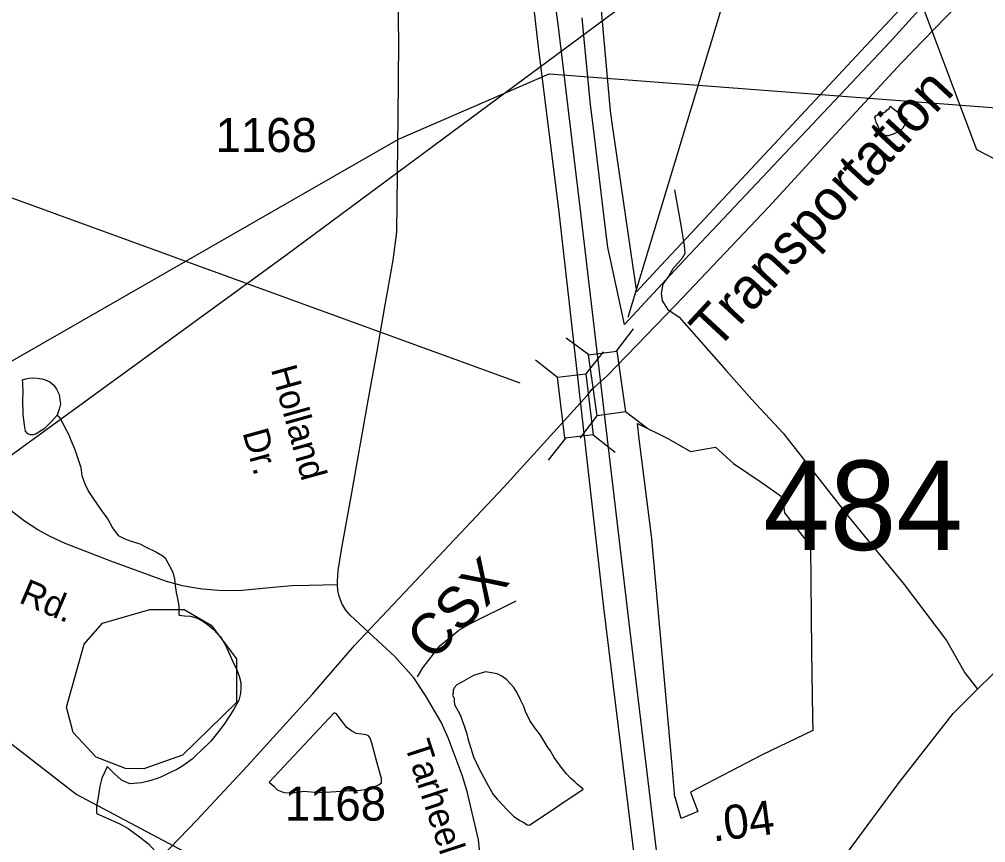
# Model space of a CAD drawing. Extents: x 2082433 to 2279600, y 546599 to 755198.
# Drawn here: x 2139852 to 2143397, y 601095 to 604115 of the extents above; entities that cross this region are included whole.
import ezdxf

# ---------------------------------------------------------------- set-up
doc = ezdxf.new("R2010")
doc.units = 0
for name, color, linetype in [('Exist Boundary Political City Limit New', 7, 'Continuous'), ('Exist Boundary Political Fire Districts', 7, 'Continuous'), ('Exist Hydrographic Creek Single Shore', 7, 'Continuous'), ('Exist Hydrographic Misc Water Feature', 7, 'Continuous'), ('Exist Hydrographic Pond Under 1500 Sq Ft', 7, 'Continuous'), ('Exist Railroad Mainline', 7, 'Continuous'), ('Exist Railroad Mainline Label', 7, 'Continuous'), ('Exist Road Non-System Type 51', 7, 'Continuous'), ('Exist Road Non-System Type 51 Label', 7, 'Continuous'), ('Exist Road Primary Interstate Divided Center Attributed', 7, 'Continuous'), ('Exist Road Primary Interstate Structure Standard Bridge CELL', 7, 'Continuous'), ('Exist Road Primary Interstate Structure Standard Bridge Number Label', 7, 'Continuous'), ('Exist Road Primary US Attributed', 7, 'Continuous'), ('Exist Road Primary US Mileage Hundredths English Label', 7, 'Continuous'), ('Exist Road Secondary Structure Standard Bridge Number Label', 7, 'Continuous'), ('Exist Road Secondary Type 51 Attributed', 7, 'Continuous'), ('Exist Road Secondary Type 51 Label', 7, 'Continuous'), ('Exist Road Secondary Type 51 Number Label', 7, 'Continuous'), ('Exist Utilities Electrical Transmission Line', 7, 'Continuous'), ('Map Preparation Boundary City Limit Buffer Line', 7, 'Continuous')]:
    doc.layers.add(name, color=color, linetype=linetype)

msp = doc.modelspace()

# ---------------------------------------------------------------- linework, layer by layer
at = {"layer": 'Exist Boundary Political City Limit New'}
for points in [[(2141956.2, 604475.9), (2142018.8, 603779.5), (2142025.5, 603733.8), (2142101.2, 603214.7), (2142115.8, 603115.7), (2142205.5, 603212.1), (2142282.5, 603294.6), (2143007, 604072.2), (2143139, 604213.8)], [(2143198, 604200.7), (2143043.2, 604030.7), (2143026.2, 604011.9), (2142271, 603210.5)], [(2142271, 603210.5), (2142072, 602996.3), (2142023.8, 603216.6), (2142022.5, 603222.9), (2142010.5, 603278.3), (2141996, 603397.6), (2141958.8, 603705.6), (2141947, 603802.1), (2141923.8, 604041.9), (2141920, 604080.1), (2141916, 604120.9)], [(2142233, 602576.2), (2142314.2, 602530.2), (2142405.5, 602546.1), (2142472, 602486.4), (2142576.8, 602414.9), (2142651.5, 602362.6), (2142658, 602305.4), (2142753.8, 602183.1), (2142756.5, 601929), (2142758, 601797.4), (2142761.5, 601554.9), (2142762.2, 601507.3), (2142576.8, 601417.4), (2142313.8, 601280.9), (2142340.2, 601209.5), (2142279.2, 601183.9), (2142258, 601261.8), (2142256.5, 601261), (2142247, 601378.5), (2142172, 602210.6), (2142126, 602576.2), (2142119.2, 602632.8), (2142233, 602576.2)]]:
    msp.add_lwpolyline(points, dxfattribs=at)
at = {"layer": 'Exist Boundary Political Fire Districts'}
msp.add_lwpolyline([(2125185.8, 609236.3), (2127409.2, 608956.3), (2130289.8, 608255.9), (2136376.8, 600637.7), (2139465.5, 602656.7), (2141242.8, 603675.4), (2141795.1, 603915), (2144979.3, 603672.9), (2148226.1, 607636.4), (2150227.4, 608573.5)], dxfattribs=at)
at = {"layer": 'Exist Hydrographic Creek Single Shore'}
msp.add_lwpolyline([(2143929.9, 600141.8), (2143945.9, 600200.5), (2144129, 600324.8), (2144261.1, 600551.7), (2144234, 600985.3), (2144012.4, 602131.7), (2143753, 602490.9), (2143635.1, 602722.9), (2143643.1, 602847.4), (2143774.9, 602998.9), (2143782.9, 603182.5), (2143682, 603424), (2143615, 603507.3), (2143364, 603637), (2143154, 604195.8), (2142718.9, 604526), (2142516.9, 604966.3), (2142400, 605050.7)], dxfattribs=at)
at = {"layer": 'Exist Hydrographic Misc Water Feature'}
for points in [[(2143046.7, 603796.2), (2143106.8, 603748.6), (2143102.7, 603734.6), (2143092.8, 603716.2), (2143086.7, 603710.2), (2143076.8, 603702.4), (2143056.7, 603694.1), (2143038.9, 603688.3), (2143033, 603688.4), (2143025.2, 603689.9), (2143017.2, 603696), (2143010.6, 603700.2), (2143002.8, 603720.1), (2142994.8, 603737.9), (2142992.6, 603748), (2142990.5, 603756), (2142994.6, 603761.9), (2143028.9, 603776.2), (2143034.4, 603782.2), (2143042.8, 603788.3), (2143046.7, 603796.2)], [(2140618.9, 600976.4), (2140058.9, 601273.1), (2139824.9, 601455.1), (2139165.9, 601661.9), (2138548.8, 601808.9), (2138273.9, 601926), (2138039.7, 602098.1), (2137888.8, 602288.1), (2137686.8, 602781), (2137484.8, 603162.3), (2137342.7, 603362), (2137175.8, 603486.7), (2137066.7, 603518.5), (2136775.7, 603508)], [(2139990.4, 602663), (2139970.5, 602640.8), (2139942.4, 602613.1), (2139913.1, 602594.8), (2139902.6, 602590.7), (2139892.8, 602590.6), (2139882.9, 602594.5), (2139874.7, 602604.7), (2139870.8, 602626.7), (2139866.3, 602666.7), (2139864.1, 602716.6), (2139866.1, 602746.7), (2139864.1, 602780.6), (2139863.9, 602792.4), (2139875.8, 602796.7), (2139887.9, 602798.5), (2139899.8, 602800.8), (2139917.8, 602798.9), (2139934, 602796.8), (2139946.1, 602793), (2139963.9, 602785), (2139978.1, 602773.1), (2139988.1, 602759.1), (2139998.4, 602739.2), (2140000, 602719.1), (2140002.5, 602705), (2139998.4, 602685.3), (2139990.4, 602663)], [(2139990.4, 602663), (2139998.4, 602657.4), (2140010.7, 602635.2), (2140024.8, 602607.1), (2140032.8, 602591.3), (2140041, 602571.4), (2140052.9, 602543.7), (2140061.1, 602519.2), (2140068.9, 602497.4), (2140077.3, 602471.4), (2140081.4, 602441.6), (2140091.7, 602411.6), (2140105.6, 602383.6), (2140125.7, 602353.8), (2140136, 602338), (2140155.9, 602309.8), (2140176.4, 602282.1), (2140194, 602250.2), (2140214.5, 602222.3), (2140238.3, 602210.2), (2140258.2, 602202.3), (2140294.3, 602190.8), (2140314.2, 602180.9), (2140354.8, 602161), (2140378.8, 602147.2), (2140388.4, 602139.2), (2140390.9, 602133.2), (2140403, 602111.1), (2140414.6, 602087.4), (2140421, 602061.3), (2140423.3, 602039.1), (2140426.9, 602013.4), (2140431.5, 601991.2), (2140437.4, 601963.6), (2140437.4, 601951.4), (2140437.4, 601933.5), (2140437.6, 601929.4)], [(2140437.6, 601929.4), (2140457.3, 601927.3), (2140479.4, 601925.5), (2140501.6, 601919.8), (2140525.4, 601907.6), (2140541.8, 601895.8), (2140561.7, 601879.8), (2140579.9, 601860.1), (2140589.8, 601850.1), (2140607.8, 601820.2), (2140634.3, 601762.2), (2140642.2, 601744.4), (2140648.4, 601732.5), (2140658.4, 601706.2), (2140664.8, 601682.6), (2140664.6, 601664.3), (2140662.8, 601642.3), (2140656.6, 601618.5), (2140637.1, 601582.6), (2140603.3, 601530.1), (2140579.1, 601498), (2140553.7, 601467.8), (2140517.6, 601431.9), (2140501.6, 601417.7), (2140485.8, 601401.8), (2140451.6, 601377.4), (2140430, 601363.6), (2140402.1, 601351.2), (2140373.8, 601337.2), (2140354.2, 601329.3), (2140326.1, 601321), (2140300.4, 601315.1), (2140258.6, 601310.9), (2140248.5, 601314.8), (2140226.4, 601324.7), (2140197.9, 601350.5), (2140174.3, 601374.3)], [(2140174.3, 601374.3), (2140170, 601366.4), (2140164.3, 601352.3), (2140154.6, 601332.3), (2140146.6, 601302.3), (2140142.5, 601270.1), (2140138.8, 601248.3), (2140134.5, 601230.3), (2140134.5, 601220.1), (2140134.7, 601206.3), (2140134.5, 601202.3)], [(2140134.5, 601202.3), (2140220.9, 601164.5), (2140251.2, 601146.9), (2140287.3, 601120.8), (2140325.2, 601091.2), (2140351.1, 601063.3), (2140379.6, 601027.3), (2140411.8, 600985.6), (2140465.9, 600925.9), (2140513.9, 600882.1), (2140523.9, 600876.2)]]:
    msp.add_lwpolyline(points, dxfattribs=at)
at = {"layer": 'Exist Hydrographic Pond Under 1500 Sq Ft'}
for points in [[(2140241.8, 601367.9), (2140133.9, 601409.5), (2140049.9, 601499.7), (2140024.8, 601592.1), (2140089.8, 601823.7), (2140156.9, 601901), (2140330.8, 601950), (2140455.9, 601950.7), (2140555.9, 601893), (2140648.8, 601769.7), (2140648.8, 601609), (2140449.9, 601416.1), (2140308.8, 601366.5), (2140241.8, 601367.9)], [(2141919.9, 601292), (2141909.7, 601300), (2141897.8, 601310), (2141889.8, 601318.1), (2141873.4, 601331.9), (2141859.4, 601347.8), (2141839.8, 601371.9), (2141823.3, 601393.8), (2141813.3, 601407.5), (2141799.4, 601433.5), (2141788.9, 601447.3), (2141763.3, 601489.3), (2141742.8, 601517.1), (2141724.9, 601542.9), (2141708.5, 601577), (2141702.6, 601595), (2141690.5, 601618.7), (2141678.2, 601644.9), (2141666.3, 601665), (2141639.8, 601692.8), (2141622.2, 601706.5), (2141604.4, 601714.5), (2141584.3, 601718.3), (2141562.3, 601722.4), (2141537.9, 601714.4), (2141517.8, 601708.1), (2141474.4, 601683.8), (2141456.5, 601674), (2141446.3, 601663.7), (2141442.6, 601653.8), (2141442.6, 601643.6), (2141440.3, 601635.8), (2141446.9, 601625.9), (2141446.5, 601613.8), (2141448.7, 601601.7), (2141468.8, 601563.8), (2141484.8, 601520), (2141492.8, 601494.1), (2141496.9, 601478), (2141517.6, 601410.4), (2141537.7, 601368.4), (2141565.6, 601316.4), (2141590.2, 601272.5), (2141604.1, 601254.6), (2141642.3, 601214.8), (2141664.6, 601193.1), (2141688.2, 601177), (2141702.2, 601169.2), (2141714.5, 601161.2), (2141722.7, 601159.2), (2141919.9, 601292)], [(2141006.8, 601572.1), (2140768.4, 601316.9), (2140786.2, 601301.2), (2140798.1, 601288.9), (2140816.3, 601281.3), (2140824.5, 601279.2), (2140854.5, 601277.6), (2140894.1, 601283.7), (2140952.1, 601279.8), (2140994.1, 601282), (2141032.1, 601284.4), (2141062, 601286.3), (2141082.1, 601286.5), (2141102.4, 601288.3), (2141118, 601290.4), (2141138.3, 601294.6), (2141156.3, 601300.8), (2141172.1, 601308.6), (2141179.9, 601314.7), (2141179.9, 601330.9), (2141163.9, 601386.9), (2141153.2, 601428.6), (2141145.4, 601460.6), (2141139.1, 601478.6), (2141131.5, 601488.7), (2141117.1, 601492.5), (2141086.8, 601496.3), (2141071.2, 601504.3), (2141053, 601518), (2141025.1, 601553.9), (2141015, 601568), (2141006.8, 601572.1)]]:
    msp.add_lwpolyline(points, dxfattribs=at)
at = {"layer": 'Exist Railroad Mainline'}
for points in [[(2142008.3, 602807.8), (2142260.1, 603068.4), (2142600.3, 603425.8), (2142847.2, 603694.8), (2143087.8, 603955.7), (2143290.8, 604164.6), (2143495.9, 604377.4), (2143705, 604580.3), (2144004.8, 604884), (2144236.9, 605087.5)], [(2141935, 602736), (2141952.8, 602758.6), (2142008.3, 602807.8)], [(2141139.2, 601879.4), (2141368.4, 602122.7), (2141629.2, 602399.8), (2141935, 602736)], [(2139743.5, 600355.6), (2140058, 600703.5), (2140306.3, 600973.6), (2140502.7, 601177.8), (2140687.7, 601376.4), (2140927.3, 601639.9), (2141081.3, 601818.2), (2141139.2, 601879.4)]]:
    msp.add_lwpolyline(points, dxfattribs=at)
at = {"layer": 'Exist Road Non-System Type 51'}
for points in [[(2142254.6, 603489.5), (2142278.6, 603359.7), (2142291, 603285), (2142293, 603256.9), (2142285.4, 603241.8), (2142249.4, 603200.4), (2142233.7, 603174.3), (2142211.7, 603144.1), (2142205.8, 603110.3), (2142210.2, 603082.9), (2142230.7, 603050.4), (2142272.6, 603023.1), (2142444.3, 602826.6), (2142538.3, 602720.7), (2142653.6, 602597.6), (2142895.4, 602288.4), (2143097.8, 602042.3), (2143252.5, 601837.3), (2143319.8, 601718.3), (2143366, 601658.2)], [(2141312.7, 601704), (2141331.4, 601736.5), (2141394.5, 601817.3), (2141463.5, 601874.5), (2141504.9, 601898.2), (2141674.4, 601982.9)]]:
    msp.add_lwpolyline(points, dxfattribs=at)
at = {"layer": 'Exist Road Primary Interstate Divided Center Attributed'}
for points in [[(2142289.3, 600244.4), (2142193.2, 601036.8), (2142088.2, 601902), (2141909.3, 603424.4), (2141828.1, 604097.7), (2141783.1, 604420.9), (2141758.2, 604671.4), (2141713.3, 604944.9), (2141667.4, 605151.5), (2141604.3, 605340.8), (2141289.8, 606102.6), (2140968.9, 606854.4), (2140672.2, 607566.5), (2140580.2, 607781.9), (2140439.4, 608117.8)], [(2140405.1, 608012.7), (2140582, 607576.6), (2140889.2, 606863.6), (2141159.6, 606209.1), (2141502.9, 605392.5), (2141566, 605203.1), (2141615.8, 605031), (2141646.4, 604902.9), (2141677, 604700.1), (2141755.4, 604013.5), (2141829, 603418.7), (2141994.4, 601957.5), (2142217.1, 600147.6)]]:
    msp.add_lwpolyline(points, dxfattribs=at)
at = {"layer": 'Exist Road Primary Interstate Structure Standard Bridge CELL'}
for p, q in [((2142042.2, 602898.4), (2142104.2, 602980.5)), ((2141940.3, 602884.1), (2141858.2, 602946.1)), ((2141993.9, 602895.9), (2141930.4, 602815)), ((2141745, 602865.9), (2141825.9, 602802.4)), ((2142157.4, 602613.5), (2142075.3, 602675.5)), ((2141909.1, 602578.8), (2141971, 602660.9)), ((2141854.7, 602578.9), (2141791.2, 602497.9)), ((2141956.9, 602591.2), (2142037.8, 602527.6))]:
    msp.add_line(p, q, dxfattribs=at)
for points in [[(2141971, 602660.9), (2141939.9, 602884.1), (2142044.1, 602898.6), (2142075.3, 602675.5)], [(2141930.4, 602815), (2141957.3, 602591.2), (2141852.8, 602578.6), (2141825.9, 602802.4)]]:
    msp.add_lwpolyline(points, close=True, dxfattribs=at)
at = {"layer": 'Exist Road Primary Interstate Structure Standard Bridge Number Label'}
for p, q in [((2142085.5, 603023), (2142801, 605389.9)), ((2141689.2, 602780.9), (2139421.4, 603606.5))]:
    msp.add_line(p, q, dxfattribs=at)
at = {"layer": 'Exist Road Primary US Attributed'}
msp.add_lwpolyline([(2142431, 600436.1), (2142771.9, 600899.9), (2142962.4, 601157.6), (2143079.5, 601316.3), (2143276.8, 601569.3), (2143366, 601658.2), (2143471.9, 601760.5), (2143832.3, 602076.7), (2144263.2, 602457.9), (2144581.2, 602737.3), (2144811, 602936.1), (2144937.1, 603035.2), (2145061.1, 603119.9), (2145064.1, 603117.9), (2145164.1, 603180.5)], dxfattribs=at)
at = {"layer": 'Exist Road Secondary Type 51 Attributed'}
for points in [[(2141018.4, 602054.7), (2141021.9, 602094.1), (2141035.1, 602176.9), (2141071.2, 602378.3), (2141129, 602703.4), (2141163.9, 602898.5), (2141192.6, 603061.1), (2141222.7, 603231.3), (2141237.1, 603334.6), (2141241.6, 603757.2), (2141244.4, 604030.7), (2141241.8, 604189.5)], [(2141019, 602041), (2140913.4, 602038.4), (2140851.1, 602036.9), (2140810.2, 602033.5), (2140667.8, 602020.8), (2140628.5, 602019.4), (2140582.5, 602020.6), (2140523.8, 602025.4), (2140484, 602031.2), (2140449.9, 602037.5), (2140391.1, 602052.8), (2140187.5, 602127.3), (2140020.2, 602192.2), (2139963, 602218.9), (2139920.2, 602242.7), (2139871, 602274.6), (2139822.4, 602312.3)], [(2141548.4, 600984.3), (2141535.7, 601105.9), (2141494, 601282.7), (2141476.8, 601343.5), (2141425.1, 601480.4), (2141398.8, 601537.6), (2141341.7, 601635.5), (2141299, 601699.9), (2141229.2, 601777.9), (2141134.9, 601865), (2141065.1, 601929.3), (2141049.8, 601947.9), (2141035.1, 601972), (2141025.2, 601999.2), (2141020.7, 602020.4), (2141019, 602041), (2141018.4, 602054.7)]]:
    msp.add_lwpolyline(points, dxfattribs=at)
at = {"layer": 'Exist Utilities Electrical Transmission Line'}
msp.add_lwpolyline([(2135510.3, 599346), (2136050.3, 599742.2), (2136793.7, 600289.3), (2137523.2, 600836.5), (2138250.6, 601365.5), (2138619.3, 601637), (2138990, 601910.6), (2139364.7, 602184), (2139739.4, 602457.6), (2140486.9, 603000.7), (2140829.8, 603250.2), (2141575.1, 603803.2), (2141969.6, 604095), (2142338.3, 604368.5), (2142712.9, 604640), (2143476.4, 605209.1), (2143859, 605478.7), (2144235.8, 605746.2), (2144606.6, 606003.9), (2144985.1, 606269.4), (2145363.9, 606534.9), (2145742.6, 606790.6), (2146119.5, 607050.1), (2146496.2, 607313.6)], dxfattribs=at)
at = {"layer": 'Map Preparation Boundary City Limit Buffer Line'}
for points in [[(2141956.2, 604475.9), (2142018.8, 603779.5), (2142025.5, 603733.8), (2142101.2, 603214.7), (2142115.8, 603115.7), (2142205.5, 603212.1), (2142282.5, 603294.6), (2143007, 604072.2), (2143139, 604213.8)], [(2143198, 604200.7), (2143043.2, 604030.7), (2143026.2, 604011.9), (2142271, 603210.5)], [(2142271, 603210.5), (2142072, 602996.3), (2142023.8, 603216.6), (2142022.5, 603222.9), (2142010.5, 603278.3), (2141996, 603397.6), (2141958.8, 603705.6), (2141947, 603802.1), (2141923.8, 604041.9), (2141920, 604080.1), (2141916, 604120.9)], [(2142233, 602576.2), (2142314.2, 602530.2), (2142405.5, 602546.1), (2142472, 602486.4), (2142576.8, 602414.9), (2142651.5, 602362.6), (2142658, 602305.4), (2142753.8, 602183.1), (2142756.5, 601929), (2142758, 601797.4), (2142761.5, 601554.9), (2142762.2, 601507.3), (2142576.8, 601417.4), (2142313.8, 601280.9), (2142340.2, 601209.5), (2142279.2, 601183.9), (2142258, 601261.8), (2142256.5, 601261), (2142247, 601378.5), (2142172, 602210.6), (2142126, 602576.2), (2142119.2, 602632.8), (2142233, 602576.2)]]:
    msp.add_lwpolyline(points, dxfattribs=at)

# ---------------------------------------------------------------- texts
at = {"layer": 'Exist Railroad Mainline Label'}
for s, rotation, p in [('Transportation', 47.2468, (2142408.5, 602897.3)), ('CSX', 45.4988, (2141366.2, 601756.2))]:
    msp.add_text(s, height=150, rotation=rotation, dxfattribs=at).set_placement(p)
at = {"layer": 'Exist Road Non-System Type 51 Label'}
for s, p in [('Holland', (2140774.1, 602832.1)), ('Dr.', (2140670, 602599.7))]:
    msp.add_text(s, height=95, rotation=285.5391, dxfattribs=at).set_placement(p)
at = {"layer": 'Exist Road Primary US Mileage Hundredths English Label'}
msp.add_text('.04', height=125, rotation=7.2278, dxfattribs=at).set_placement((2142396.6, 601098.9))
at = {"layer": 'Exist Road Secondary Structure Standard Bridge Number Label'}
msp.add_text('484', height=328.08, dxfattribs=at).set_placement((2142580.8, 602168.7))
at = {"layer": 'Exist Road Secondary Type 51 Label'}
for s, rotation, p in [('Rd.', 336.9819, (2139846.1, 601977.6)), ('Tarheel', 288.0969, (2141264, 601454.3))]:
    msp.add_text(s, height=95, rotation=rotation, dxfattribs=at).set_placement(p)
at = {"layer": 'Exist Road Secondary Type 51 Number Label'}
for p in [(2140571.4, 603628.3), (2140825.3, 601176)]:
    msp.add_text('1168', height=125, dxfattribs=at).set_placement(p)

doc.saveas('drawing.dxf')
